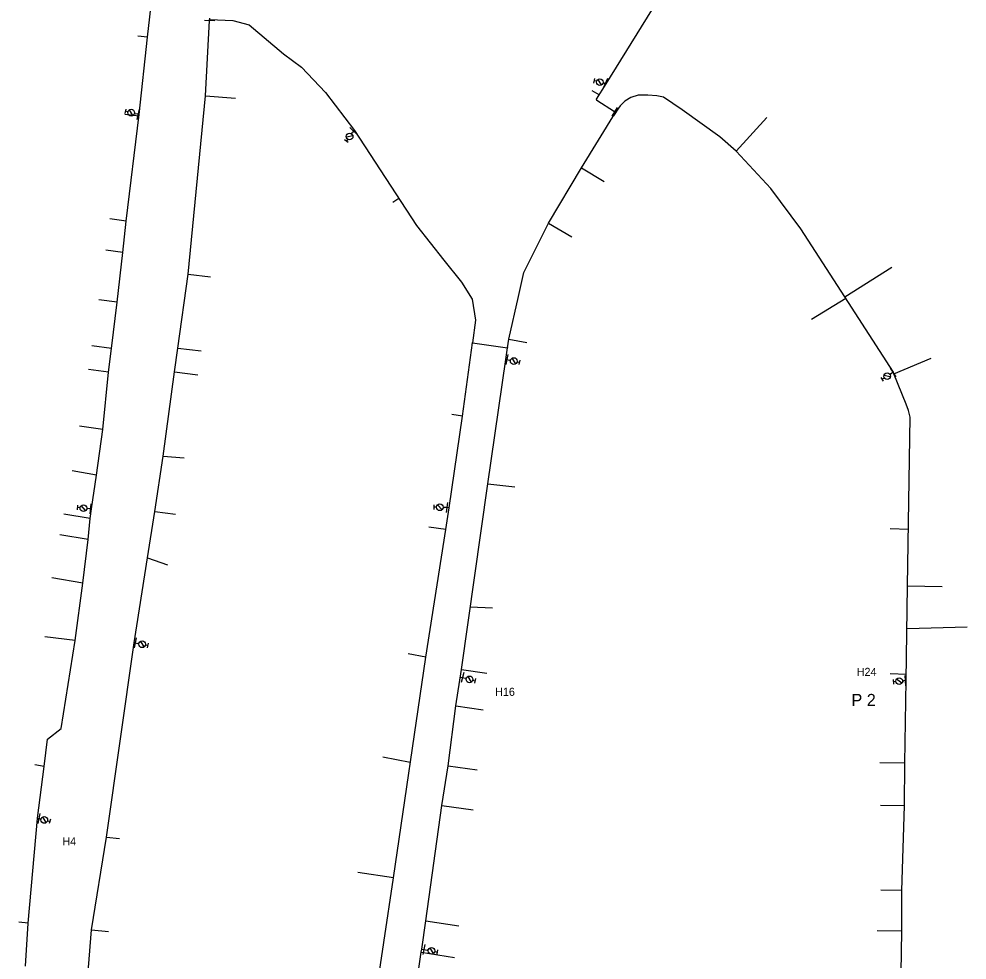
# Model space of a CAD drawing. Extents: x -548873 to -538270, y -1201997 to -1192514.
# Drawn here: x -543859.1 to -543624, y -1197239.4 to -1197006.1 of the extents above; entities that cross this region are included whole.
import ezdxf

# ---------------------------------------------------------------- set-up
doc = ezdxf.new("R2010")
doc.units = 0
for name, color, linetype in [('KN_HRAN_STÁTNÍ', 7, 'Continuous'), ('KN_PARC_Č', 7, 'Continuous'), ('KN_VKP_HRAN_SPORNÁ', 7, 'Continuous'), ('PK_PARC_Čv', 7, 'Continuous'), ('Vrstva 29', 7, 'Continuous')]:
    doc.layers.add(name, color=color, linetype=linetype)

# ---------------------------------------------------------------- blocks, each defined once
blk = doc.blocks.new('160')
at = {"layer": 'KN_HRAN_STÁTNÍ'}
blk.add_circle((0, 0), 0.0458, dxfattribs=at)
blk = doc.blocks.new('147')
at = {"layer": 'KN_HRAN_STÁTNÍ'}
blk.add_line((0, 1.27), (0, -1.27), dxfattribs=at)
blk = doc.blocks.new('133')
at = {"layer": 'KN_HRAN_STÁTNÍ'}
for p, q in [((0.28, 0), (0, 0)), ((0.54, 0.58), (1.7, -0.58)), ((1.94, 0), (2.52, 0)), ((2.52, 0.58), (2.52, -0.58))]:
    blk.add_line(p, q, dxfattribs=at)
blk.add_circle((1.11, 0), 0.825, dxfattribs=at)
blk = doc.blocks.new('150')
at = {"layer": 'KN_HRAN_STÁTNÍ'}
blk.add_line((0, 1.27), (0, -1.27), dxfattribs=at)

msp = doc.modelspace()

# ---------------------------------------------------------------- linework, layer by layer
at = {"layer": 'KN_PARC_Č'}
for points in [[(-543827.182, -1197010.643), (-543829.634, -1197010.375)], [(-543715.197, -1197024.991), (-543716.942, -1197023.924)], [(-543812.809, -1197025.216), (-543805.415, -1197025.813)], [(-543829.329, -1197030.261), (-543832.873, -1197029.843)], [(-543681.251, -1197038.933), (-543673.652, -1197030.606)], [(-543719.631, -1197043.092), (-543713.959, -1197046.427)], [(-543764.886, -1197050.663), (-543766.426, -1197051.622)], [(-543832.533, -1197056.25), (-543836.546, -1197055.715)], [(-543727.751, -1197056.732), (-543722.04, -1197060.125)], [(-543833.303, -1197064.02), (-543837.551, -1197063.443)], [(-543654.284, -1197075.053), (-543642.703, -1197067.654)], [(-543817.149, -1197069.406), (-543811.589, -1197070.056)], [(-543834.773, -1197076.34), (-543839.257, -1197075.737)], [(-543654.051, -1197075.415), (-543662.585, -1197080.627)], [(-543836.153, -1197087.84), (-543840.99, -1197087.191)], [(-543737.645, -1197085.545), (-543733.192, -1197086.372)], [(-543819.709, -1197087.726), (-543813.946, -1197088.4)], [(-543642.126, -1197094.138), (-543632.886, -1197090.253)], [(-543836.893, -1197093.73), (-543841.823, -1197093.062)], [(-543820.509, -1197093.656), (-543814.732, -1197094.384)], [(-543749.103, -1197104.623), (-543751.797, -1197104.24)], [(-543838.323, -1197107.88), (-543844.104, -1197107.104)], [(-543823.349, -1197114.516), (-543818.11, -1197114.972)], [(-543839.844, -1197119.199), (-543845.91, -1197118.19)], [(-543742.817, -1197121.426), (-543736.108, -1197122.1)], [(-543841.474, -1197129.969), (-543847.96, -1197128.9)], [(-543825.399, -1197128.226), (-543820.266, -1197128.93)], [(-543753.243, -1197132.741), (-543757.46, -1197132.167)], [(-543841.914, -1197135.179), (-543848.993, -1197133.998)], [(-543638.55, -1197132.685), (-543643.061, -1197132.552)], [(-543827.216, -1197139.744), (-543822.273, -1197141.496)], [(-543843.254, -1197145.989), (-543850.909, -1197144.724)], [(-543638.75, -1197146.696), (-543630.169, -1197146.822)], [(-543747.176, -1197151.867), (-543741.682, -1197152.153)], [(-543638.898, -1197157.225), (-543624.016, -1197156.847)], [(-543845.124, -1197160.259), (-543852.672, -1197159.291)], [(-543758.213, -1197164.321), (-543762.545, -1197163.544)], [(-543749.397, -1197167.376), (-543743.092, -1197168.281)], [(-543639.058, -1197168.616), (-543643.056, -1197168.484)], [(-543750.797, -1197176.416), (-543743.997, -1197177.413)], [(-543852.814, -1197191.449), (-543855.165, -1197191.06)], [(-543762.063, -1197190.498), (-543768.864, -1197189.166)], [(-543639.42, -1197190.644), (-543645.663, -1197190.568)], [(-543752.697, -1197191.266), (-543745.513, -1197192.295)], [(-543754.257, -1197201.116), (-543746.508, -1197202.231)], [(-543639.55, -1197201.184), (-543645.449, -1197201.095)], [(-543837.368, -1197208.97), (-543834.162, -1197209.296)], [(-543766.263, -1197219.061), (-543775.065, -1197217.707)], [(-543640.18, -1197222.204), (-543645.379, -1197222.122)], [(-543856.822, -1197230.271), (-543859.088, -1197230.04)], [(-543758.207, -1197229.716), (-543750.002, -1197230.936)], [(-543841.128, -1197231.94), (-543836.855, -1197232.365)], [(-543640.2, -1197232.264), (-543646.306, -1197232.192)], [(-543759.327, -1197237.506), (-543751.13, -1197238.796)]]:
    msp.add_lwpolyline(points, dxfattribs=at)
at = {"layer": 'KN_VKP_HRAN_SPORNÁ'}
for points in [[(-543711.418, -1197029.171), (-543715.835, -1197026.344), (-543715.857, -1197026.024), (-543713.453, -1197022.265), (-543691.897, -1196987.355), (-543684.72, -1196973.75)], [(-543857.503, -1197240.922), (-543856.822, -1197230.271), (-543854.455, -1197204.345), (-543854.451, -1197204.297), (-543852.814, -1197191.449), (-543852.027, -1197184.641), (-543848.636, -1197182.026), (-543845.124, -1197160.259), (-543843.254, -1197145.989), (-543841.914, -1197135.179), (-543841.474, -1197129.969), (-543841.082, -1197127.602), (-543839.844, -1197119.199), (-543838.323, -1197107.88), (-543836.893, -1197093.73), (-543836.153, -1197087.84), (-543834.773, -1197076.34), (-543833.303, -1197064.02), (-543832.533, -1197056.25), (-543829.278, -1197029.85), (-543829.275, -1197029.822), (-543827.182, -1197010.643), (-543826.042, -1197000.461)], [(-543843.69, -1197292.623), (-543844.321, -1197285.713), (-543844.331, -1197279.136), (-543844.015, -1197268.092), (-543842.758, -1197252.703), (-543841.128, -1197231.94), (-543837.368, -1197208.97), (-543830.534, -1197160.782), (-543827.218, -1197139.758), (-543825.399, -1197128.226), (-543823.349, -1197114.516), (-543820.509, -1197093.656), (-543819.709, -1197087.726), (-543817.149, -1197069.406), (-543812.809, -1197025.216), (-543811.809, -1197006.557)], [(-543811.797, -1197006.316), (-543811.809, -1197006.557)], [(-543811.797, -1197006.316), (-543811.779, -1197005.986)], [(-543811.797, -1197006.316), (-543806.045, -1197006.556), (-543802.008, -1197007.622), (-543793.506, -1197014.782), (-543789.047, -1197018.078), (-543783.113, -1197024.412), (-543775.918, -1197033.763), (-543760.54, -1197057.32), (-543753.72, -1197065.95), (-543749.375, -1197071.375), (-543746.692, -1197075.61), (-543745.899, -1197080.78), (-543746.662, -1197086.457)], [(-543640.56, -1197258.168), (-543640.2, -1197232.264), (-543640.18, -1197222.204), (-543639.55, -1197201.184), (-543639.42, -1197190.644), (-543639.08, -1197170.174), (-543638.75, -1197146.696), (-543638.154, -1197104.84), (-543638.505, -1197103.219), (-543639.09, -1197101.632), (-543642.126, -1197094.138), (-543642.279, -1197093.703), (-543654.284, -1197075.053), (-543665.216, -1197058.148), (-543672.682, -1197048.149), (-543681.251, -1197038.933), (-543685.308, -1197035.353), (-543694.652, -1197028.647), (-543699.292, -1197025.575), (-543700.942, -1197025.207), (-543703.155, -1197025.018), (-543705.52, -1197025.029), (-543707.353, -1197025.583), (-543708.89, -1197026.554), (-543710.038, -1197027.719), (-543710.98, -1197029.06)], [(-543737.951, -1197087.666), (-543737.645, -1197085.545), (-543735.207, -1197074.921), (-543733.947, -1197068.958), (-543727.751, -1197056.732), (-543719.631, -1197043.092), (-543711.153, -1197029.341)], [(-543711.153, -1197029.341), (-543711.418, -1197029.171)], [(-543710.98, -1197029.06), (-543711.153, -1197029.341)], [(-543780.016, -1197367.421), (-543786.509, -1197366.152), (-543786.708, -1197365.832), (-543779.543, -1197314.411), (-543775.603, -1197288.341), (-543774.603, -1197278.471), (-543773.931, -1197271.87), (-543773.453, -1197267.171), (-543771.053, -1197251.114), (-543766.263, -1197219.061), (-543758.213, -1197164.321), (-543753.243, -1197132.741), (-543752.45, -1197127.353), (-543749.103, -1197104.623), (-543746.662, -1197086.457)], [(-543779.401, -1197366.702), (-543778.536, -1197360.954), (-543775.593, -1197343.274), (-543775.443, -1197342.425), (-543774.231, -1197340.177), (-543772.93, -1197331.524), (-543771.755, -1197322.145), (-543768.865, -1197302.775), (-543764.427, -1197272.946), (-543761.637, -1197253.506), (-543759.327, -1197237.506), (-543759.217, -1197236.758), (-543758.207, -1197229.716), (-543754.257, -1197201.116), (-543752.697, -1197191.266), (-543750.797, -1197176.416), (-543749.397, -1197167.376), (-543742.817, -1197121.426), (-543738.367, -1197090.554), (-543737.951, -1197087.666)], [(-543746.662, -1197086.457), (-543737.951, -1197087.666)]]:
    msp.add_lwpolyline(points, dxfattribs=at)
at = {"layer": 'PK_PARC_Čv'}
for points in [[(-543713.454, -1197022.266), (-543713.71, -1197022.11), (-543713.99, -1197022.05)], [(-543829.275, -1197029.822), (-543829.57, -1197029.782), (-543830.18, -1197029.64)], [(-543775.918, -1197033.763), (-543776.16, -1197033.94), (-543776.465, -1197034.371)], [(-543738.367, -1197090.554), (-543738.15, -1197090.58), (-543737.499, -1197090.712)], [(-543642.277, -1197093.709), (-543642.91, -1197094.109)], [(-543841.082, -1197127.602), (-543841.381, -1197127.575), (-543842.006, -1197127.518)], [(-543752.45, -1197127.353), (-543752.99, -1197127.26), (-543753.635, -1197127.236)], [(-543830.534, -1197160.782), (-543830.237, -1197160.822), (-543829.638, -1197160.927)], [(-543749.691, -1197169.274), (-543749.109, -1197169.42), (-543748.48, -1197169.578)], [(-543639.08, -1197170.174), (-543639.38, -1197170.17), (-543639.71, -1197170.2)], [(-543854.455, -1197204.345), (-543854.16, -1197204.37), (-543853.88, -1197204.44)], [(-543759.217, -1197236.758), (-543758.729, -1197236.83), (-543757.902, -1197236.952)]]:
    msp.add_lwpolyline(points, dxfattribs=at)

# ---------------------------------------------------------------- block references
for name, p, xscale, yscale, rotation in [('133', (-543713.99, -1197022.05), 1.0045862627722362, 1.0045862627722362, 166.82590928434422), ('150', (-543713.71, -1197022.11), 1.0275072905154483, 1.027507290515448, -24.689105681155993), ('133', (-543830.18, -1197029.64), 1.0028916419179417, 1.0028916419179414, 166.30279126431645), ('150', (-543829.57, -1197029.782), 1.0073309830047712, 1.0073309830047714, -12.13890866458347), ('150', (-543776.16, -1197033.94), 1.0000000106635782, 1.0000000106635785, 45.99999834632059), ('133', (-543776.465, -1197034.371), 1.000000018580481, 1.000000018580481, -125.00000023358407), ('150', (-543738.15, -1197090.58), 1.008377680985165, 1.0083776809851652, -11.626378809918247), ('133', (-543737.499, -1197090.712), 1.0060666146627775, 1.0060666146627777, -12.654735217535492), ('133', (-543642.91, -1197094.109), 0.9999999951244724, 0.9999999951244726, -146.99999872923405), ('150', (-543642.39, -1197093.78), 0.9999999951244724, 0.9999999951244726, 33.000001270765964), ('133', (-543842.006, -1197127.518), 1.0018265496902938, 1.0018265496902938, 173.92187301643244), ('150', (-543841.381, -1197127.575), 1.0018265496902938, 1.0018265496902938, -6.078126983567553), ('133', (-543753.635, -1197127.236), 1.00000001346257, 1.0000000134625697, 178.0000000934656), ('150', (-543752.99, -1197127.26), 1.0018265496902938, 1.0018265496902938, -6.078126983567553), ('150', (-543830.237, -1197160.822), 1.0092050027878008, 1.0092050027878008, -11.116918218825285), ('133', (-543829.638, -1197160.927), 1.008377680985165, 1.0083776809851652, -11.626378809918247), ('150', (-543749.109, -1197169.42), 1.0009848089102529, 1.000984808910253, -14.224326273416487), ('133', (-543748.48, -1197169.578), 1.0009848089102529, 1.000984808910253, -14.224326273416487), ('133', (-543639.71, -1197170.2), 1.0011217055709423, 1.0011217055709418, -173.41739016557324), ('150', (-543639.38, -1197170.17), 1.0002788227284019, 1.0002788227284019, 3.2906995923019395), ('150', (-543854.16, -1197204.37), 1.008377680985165, 1.0083776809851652, -11.626378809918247), ('133', (-543853.88, -1197204.44), 1.0009848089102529, 1.000984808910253, -14.224326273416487), ('150', (-543758.729, -1197236.83), 1.0092050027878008, 1.0092050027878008, -11.116918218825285), ('133', (-543757.902, -1197236.952), 1.0092050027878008, 1.0092050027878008, -11.116918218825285)]:
    msp.add_blockref(name, p, dxfattribs=dict(at, xscale=xscale, yscale=yscale, rotation=rotation))
at = {"layer": 'Vrstva 29'}
for name, p, xscale, yscale, rotation in [('147', (-543811.809, -1197006.557), 0.9999999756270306, 0.9999999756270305, -93.00000001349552), ('160', (-543811.797, -1197006.316), 0.9999999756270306, 0.9999999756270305, -93.00000001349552), ('147', (-543711.418, -1197029.171), 0.9999999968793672, 0.9999999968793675, -32.00000027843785), ('147', (-543710.98, -1197029.06), 0.9999999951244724, 0.9999999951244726, -33.000001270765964), ('160', (-543711.153, -1197029.341), 0.9999999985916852, 0.9999999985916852, 103.00000027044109), ('160', (-543746.662, -1197086.457), 1.000191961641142, 1.000191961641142, -97.08900113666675), ('160', (-543737.951, -1197087.666), 0.9999999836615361, 0.9999999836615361, 81.99999961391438)]:
    msp.add_blockref(name, p, dxfattribs=dict(at, xscale=xscale, yscale=yscale, rotation=rotation))

# ---------------------------------------------------------------- texts
at = {"layer": 'PK_PARC_Čv'}
for s, height, p in [('H24', 2, (-543651.37, -1197169)), ('H16', 2, (-543741.03, -1197173.948)), ('P 2', 3, (-543652.67, -1197176.46)), ('H4', 2, (-543848.33, -1197211.01))]:
    msp.add_text(s, height=height, dxfattribs=at).set_placement(p)

doc.saveas('drawing.dxf')
